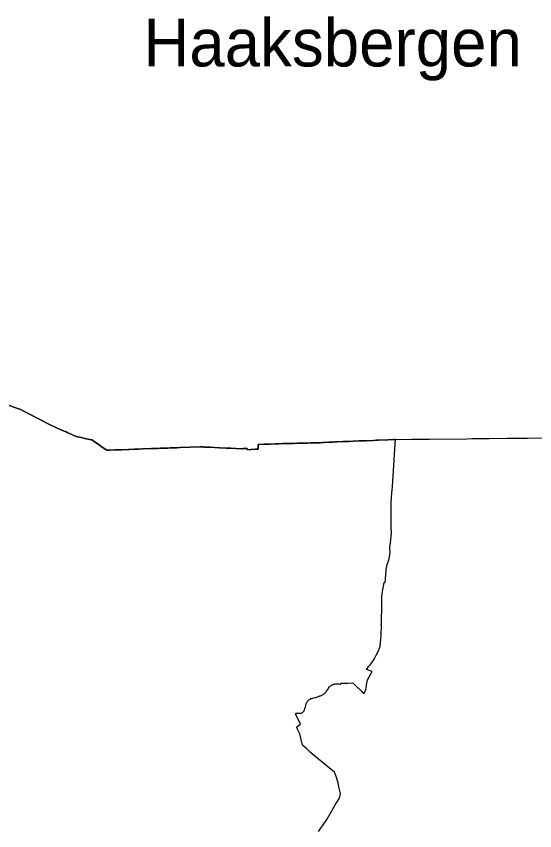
# Model space of a CAD drawing. Extents: x 113371 to 291721, y 393993 to 520143.
# Drawn here: x 245048 to 250494, y 455750 to 464302 of the extents above; entities that cross this region are included whole.
import ezdxf

# ---------------------------------------------------------------- set-up
doc = ezdxf.new("R2010")
doc.units = 0
doc.layers.add('Default', color=7, linetype='Continuous')
doc.layers.add('plaatsnamen', color=7, linetype='Continuous')

msp = doc.modelspace()

# ---------------------------------------------------------------- linework, layer by layer
at = {"layer": 'Default'}
for points in [[(245632.235625, 459909.5825), (245581.605625, 459932.2525), (245581.445625, 459932.3225), (245570.375625, 459937.2225), (245550.985625, 459945.7825), (245478.225625, 459977.9525), (245450.665625, 459990.1325), (245417.505625, 460004.5125), (245395.415625, 460014.0925), (245099.235625, 460169.0625), (245094.315625, 460171.5525), (245083.585625, 460175.5825), (245071.705625, 460180.0525), (244938.645625, 460230.0925)], [(244938.645625, 460230.0925), (245071.705625, 460180.0525), (245083.585625, 460175.5825), (245094.315625, 460171.5525), (245099.235625, 460169.0625), (245395.415625, 460014.0925), (245417.505625, 460004.5125), (245450.665625, 459990.1325), (245478.225625, 459977.9525), (245550.985625, 459945.7825), (245570.375625, 459937.2225), (245581.445625, 459932.3225), (245581.605625, 459932.2525), (245632.235625, 459909.5825), (245651.635625, 459901.3225), (245670.595625, 459892.5425), (245677.315625, 459890.9925), (245677.605625, 459890.9225), (245730.945625, 459878.6125), (245781.805625, 459866.2725), (245839.935625, 459853.1725), (245910.985625, 459805.0225), (245934.645625, 459789.5525), (245939.525625, 459786.2725), (245999.695625, 459745.7925), (246030.245625, 459746.5525), (246085.795625, 459748.4625), (246120.305625, 459750.3025), (246122.365625, 459750.2925), (246125.915625, 459750.2825), (246126.945625, 459750.2825), (246152.785625, 459750.9225), (246225.045625, 459753.6325), (246236.055625, 459753.7425), (246284.385625, 459755.4425), (246332.885625, 459757.3625), (246378.135625, 459759.1425)], [(246726.125625, 459771.2425), (246725.855625, 459771.2325), (246725.795625, 459771.2325), (246720.375625, 459771.0425), (246714.945625, 459770.8625), (246714.035625, 459770.8325), (246669.895625, 459769.3325), (246666.585625, 459769.2125), (246664.055625, 459769.1225), (246638.825625, 459768.2325), (246564.325625, 459765.5825), (246538.825625, 459764.8725), (246534.025625, 459764.7425), (246469.275625, 459762.9425), (246378.135625, 459759.1425), (246332.885625, 459757.3625), (246284.385625, 459755.4425), (246236.055625, 459753.7425), (246225.045625, 459753.6325), (246152.785625, 459750.9225), (246126.945625, 459750.2825), (246125.915625, 459750.2825), (246122.365625, 459750.2925), (246120.305625, 459750.3025), (246085.795625, 459748.4625), (246030.245625, 459746.5525), (245999.695625, 459745.7925), (245939.525625, 459786.2725), (245934.645625, 459789.5525), (245910.985625, 459805.0225), (245839.935625, 459853.1725), (245781.805625, 459866.2725), (245730.945625, 459878.6125), (245677.605625, 459890.9225), (245677.315625, 459890.9925), (245670.595625, 459892.5425), (245651.635625, 459901.3225), (245632.235625, 459909.5825)], [(247849.665625, 459814.9125), (247809.575625, 459813.1025), (247804.315625, 459812.9625), (247769.175625, 459812.0625), (247715.685625, 459810.6925), (247714.085625, 459810.6425), (247651.205625, 459808.8025), (247650.675625, 459808.7825), (247590.185625, 459807.0125), (247590.245625, 459756.7525), (247559.215625, 459755.4525), (247510.195625, 459752.8025), (247477.365625, 459750.7225), (247473.665625, 459764.9525), (247431.995625, 459762.7325), (247412.435625, 459761.3325), (247409.025625, 459761.8325), (247303.035625, 459766.3225), (247265.155625, 459768.2225), (247264.645625, 459768.2425), (247255.265625, 459768.7025), (247253.785625, 459768.7825), (247253.545625, 459768.7925), (247182.185625, 459771.8525), (247080.735625, 459776.4525), (247049.085625, 459777.8225), (247019.375625, 459779.2025), (247009.105625, 459779.6825), (247008.155625, 459779.7325), (247007.555625, 459779.7525), (246998.105625, 459780.1925), (246989.705625, 459780.4025), (246977.915625, 459779.8425), (246874.355625, 459776.3625), (246770.895625, 459772.7625), (246733.865625, 459771.5025), (246726.175625, 459771.2425), (246726.125625, 459771.2425)], [(247431.995625, 459762.7325), (247473.665625, 459764.9525), (247477.365625, 459750.7225), (247510.195625, 459752.8025), (247559.215625, 459755.4525), (247590.245625, 459756.7525), (247590.185625, 459807.0125), (247650.675625, 459808.7825), (247651.205625, 459808.8025), (247714.085625, 459810.6425), (247715.685625, 459810.6925), (247769.175625, 459812.0625), (247804.315625, 459812.9625), (247809.575625, 459813.1025), (247849.665625, 459814.9125), (247886.165625, 459815.5525), (247891.025625, 459815.6325), (247921.135625, 459816.5325), (247930.885625, 459816.8225), (247954.705625, 459817.2125), (247960.845625, 459817.3125), (247997.445625, 459818.2025), (248038.125625, 459819.2025), (248104.805625, 459821.2625), (248140.065625, 459821.8325), (248199.195625, 459823.6225), (248232.185625, 459824.6225), (248238.795625, 459824.8225), (248239.755625, 459824.8525), (248266.185625, 459826.2025)], [(249021.365625, 459699.9125), (249032.395625, 459858.9725), (249009.645625, 459858.2425), (248950.145625, 459855.4625), (248847.875625, 459851.1425), (248835.035625, 459850.5925), (248833.555625, 459850.5425), (248799.065625, 459849.3025), (248721.935625, 459845.7425), (248684.765625, 459843.8625), (248651.285625, 459842.5625), (248587.855625, 459840.1125), (248541.525625, 459838.0125), (248541.325625, 459838.0025), (248478.085625, 459835.4025), (248419.905625, 459832.9725), (248418.725625, 459832.9325), (248398.595625, 459831.9625), (248377.955625, 459830.9625), (248366.255625, 459830.3925), (248332.755625, 459829.0325), (248277.055625, 459826.7625), (248266.185625, 459826.2025), (248239.755625, 459824.8525), (248238.795625, 459824.8225), (248232.185625, 459824.6225), (248199.195625, 459823.6225), (248140.065625, 459821.8325), (248104.805625, 459821.2625), (248038.125625, 459819.2025), (247997.445625, 459818.2025), (247960.845625, 459817.3125), (247954.705625, 459817.2125), (247930.885625, 459816.8225), (247921.135625, 459816.5325), (247891.025625, 459815.6325), (247886.165625, 459815.5525), (247849.665625, 459814.9125)], [(248266.185625, 459826.2025), (248277.055625, 459826.7625), (248332.755625, 459829.0325), (248366.255625, 459830.3925), (248377.955625, 459830.9625), (248398.595625, 459831.9625), (248418.725625, 459832.9325), (248419.905625, 459832.9725), (248478.085625, 459835.4025), (248541.325625, 459838.0025), (248541.525625, 459838.0125), (248587.855625, 459840.1125), (248651.285625, 459842.5625), (248684.765625, 459843.8625), (248721.935625, 459845.7425), (248799.065625, 459849.3025), (248833.555625, 459850.5425), (248835.035625, 459850.5925), (248847.875625, 459851.1425), (248950.145625, 459855.4625), (249009.645625, 459858.2425), (249032.395625, 459858.9725), (249208.575625, 459860.7325), (249213.045625, 459860.7825), (249216.725625, 459860.8125), (249224.285625, 459860.8925), (249389.745625, 459862.5425), (249779.685625, 459866.3925), (249840.825625, 459868.2225), (249864.025625, 459868.9225), (249875.055625, 459868.9125), (249910.755625, 459868.9125), (250017.215625, 459868.9025), (250203.375625, 459870.9425), (250203.535625, 459870.9425), (250227.385625, 459871.1625), (250230.205625, 459871.1925), (250415.405625, 459872.9125)], [(250415.405625, 459872.9125), (250627.735625, 459874.8825)], [(246378.135625, 459759.1425), (246469.275625, 459762.9425), (246534.025625, 459764.7425), (246538.825625, 459764.8725), (246564.325625, 459765.5825), (246638.825625, 459768.2325), (246664.055625, 459769.1225), (246666.585625, 459769.2125), (246669.895625, 459769.3325), (246714.035625, 459770.8325), (246714.945625, 459770.8625), (246720.375625, 459771.0425), (246725.795625, 459771.2325), (246725.855625, 459771.2325), (246726.125625, 459771.2425), (246726.175625, 459771.2425), (246733.865625, 459771.5025), (246770.895625, 459772.7625), (246874.355625, 459776.3625), (246977.915625, 459779.8425), (246989.705625, 459780.4025), (246998.105625, 459780.1925), (247007.555625, 459779.7525), (247008.155625, 459779.7325), (247009.105625, 459779.6825), (247019.375625, 459779.2025), (247049.085625, 459777.8225), (247080.735625, 459776.4525), (247182.185625, 459771.8525), (247253.545625, 459768.7925), (247253.785625, 459768.7825), (247255.265625, 459768.7025), (247264.645625, 459768.2425), (247265.155625, 459768.2225), (247303.035625, 459766.3225), (247409.025625, 459761.8325), (247412.435625, 459761.3325), (247431.995625, 459762.7325)], [(248889.615625, 458128.3825), (248888.105625, 458176.6725), (248889.225625, 458207.4525), (248895.005625, 458260.1525), (248899.305625, 458283.6225), (248906.605625, 458319.1825), (248911.215625, 458358.0025), (248923.275625, 458356.4325), (248933.145625, 458479.8825), (248934.265625, 458498.5825), (248940.665625, 458525.1125), (248945.675625, 458545.8625), (248956.965625, 458583.6225), (248964.395625, 458606.4025), (248974.135625, 458672.1325), (248972.945625, 458709.1925), (248971.945625, 458727.7425), (248979.075625, 458771.4725), (248983.975625, 458803.4025), (248986.385625, 458838.7625), (248988.335625, 458878.7325), (248987.305625, 458937.8125), (248986.015625, 459036.9225), (248984.845625, 459070.7025), (248985.275625, 459100.9425), (248986.165625, 459209.7725), (248988.755625, 459241.3325), (248993.775625, 459301.2225), (248996.205625, 459325.3425), (248999.395625, 459362.8625), (249004.365625, 459427.1325), (249007.085625, 459471.8925), (249007.265625, 459475.0025), (249010.485625, 459527.8125), (249017.885625, 459649.5625), (249017.915625, 459650.0425), (249021.315625, 459699.1925), (249021.365625, 459699.9125)], [(248579.325625, 457302.0625), (248579.905625, 457302.0825), (248582.145625, 457302.1325), (248618.195625, 457268.6025), (248675.555625, 457215.2625), (248701.115625, 457191.0825), (248718.305625, 457233.5425), (248724.245625, 457253.8125), (248727.565625, 457272.0325), (248727.635625, 457272.8425), (248730.285625, 457302.1825), (248733.295625, 457319.8125), (248742.455625, 457342.8325), (248786.005625, 457422.6725), (248728.215625, 457443.6925), (248753.235625, 457476.7125), (248767.335625, 457495.3225), (248770.365625, 457498.1425), (248775.675625, 457503.3625), (248776.805625, 457504.5525), (248800.915625, 457540.5125), (248814.375625, 457564.5325), (248830.005625, 457593.7925), (248852.855625, 457640.4725), (248863.945625, 457667.8825), (248871.615625, 457686.8325), (248870.375625, 457696.7125), (248875.005625, 457720.7425), (248876.205625, 457760.5025), (248881.015625, 457803.0225), (248882.265625, 457829.9325), (248881.325625, 457849.9725), (248883.165625, 457864.9625), (248883.505625, 457871.2725), (248882.945625, 457902.9625), (248882.435625, 457913.6225), (248883.135625, 457921.9725), (248889.615625, 458128.3825)], [(248265.675625, 457177.4725), (248270.785625, 457179.8525), (248274.905625, 457182.7025), (248280.775625, 457186.9825), (248287.075625, 457191.6825), (248289.735625, 457194.2925), (248294.335625, 457199.7425), (248298.875625, 457204.7025), (248302.315625, 457209.3625), (248306.545625, 457216.1825), (248312.715625, 457224.9525), (248319.625625, 457234.4725), (248324.765625, 457242.5125), (248339.995625, 457262.9125), (248343.305625, 457266.7125), (248346.135625, 457269.2725), (248350.715625, 457272.7925), (248355.675625, 457276.4425), (248359.335625, 457278.7925), (248363.955625, 457281.1725), (248368.985625, 457283.4125), (248375.915625, 457286.8325), (248380.005625, 457287.9225), (248385.425625, 457289.4725), (248394.655625, 457290.8425), (248400.745625, 457292.1125), (248406.435625, 457292.8725), (248414.595625, 457293.3825), (248422.845625, 457293.2125), (248429.955625, 457293.2725), (248435.575625, 457293.0725), (248435.825625, 457292.9925), (248447.755625, 457290.3825), (248454.215625, 457289.0825), (248458.625625, 457298.7125), (248525.385625, 457300.7125), (248531.445625, 457300.8925), (248579.325625, 457302.0625)], [(248061.845625, 456998.2325), (248065.725625, 457002.6025), (248068.565625, 457006.1725), (248070.705625, 457009.0625), (248072.545625, 457013.5025), (248074.945625, 457019.2725), (248079.685625, 457035.0125), (248084.855625, 457050.9925), (248089.455625, 457065.9225), (248093.945625, 457081.9925), (248096.705625, 457089.8725), (248099.055625, 457095.1125), (248100.985625, 457099.3025), (248103.865625, 457103.9325), (248106.845625, 457108.3125), (248110.915625, 457113.4225), (248115.185625, 457118.6825), (248118.555625, 457121.8925), (248121.955625, 457125.0225), (248125.105625, 457127.2925), (248128.875625, 457129.9225), (248133.755625, 457132.1825), (248138.695625, 457135.0325), (248143.905625, 457137.0525), (248150.465625, 457139.1325), (248163.825625, 457142.5825), (248171.675625, 457144.9525), (248186.145625, 457148.9125), (248193.965625, 457150.8125), (248201.695625, 457153.3425), (248209.035625, 457155.8525), (248222.825625, 457160.2625), (248229.865625, 457162.5625), (248236.665625, 457164.9625), (248242.615625, 457166.8925), (248249.105625, 457169.8525), (248257.775625, 457173.7525), (248265.675625, 457177.4725)], [(248399.455625, 456020.7825), (248442.165625, 456092.6925), (248452.445625, 456141.8925), (248436.375625, 456212.3925), (248431.325625, 456235.0025), (248427.615625, 456251.5925), (248406.865625, 456319.4925), (248391.865625, 456366.7525), (248301.315625, 456440.0625), (248184.665625, 456534.7425), (248141.265625, 456569.5225), (248095.005625, 456612.4525), (248082.255625, 456624.2525), (248059.735625, 456645.3925), (248056.375625, 456652.8325), (248052.665625, 456662.8125), (248050.675625, 456668.1825), (248048.405625, 456676.5225), (248027.835625, 456767.5525), (247993.165625, 456837.1125), (248034.515625, 456869.2325), (247986.275625, 456970.9825), (247985.005625, 456974.5825), (247985.285625, 456980.4025), (247987.105625, 456983.4525), (247993.285625, 456983.8725), (248004.055625, 456984.4425), (248018.155625, 456984.5625), (248026.995625, 456984.4425), (248031.955625, 456984.5225), (248037.165625, 456984.5325), (248040.405625, 456984.8225), (248042.395625, 456985.3325), (248045.625625, 456986.4925), (248049.025625, 456987.8925), (248053.885625, 456991.2525), (248058.205625, 456994.7925), (248061.845625, 456998.2325)], [(248221.715625, 455742.2925), (248296.085625, 455847.9225), (248303.495625, 455858.4425), (248310.465625, 455869.5525), (248361.925625, 455957.6025), (248399.455625, 456020.7825)]]:
    msp.add_lwpolyline(points, dxfattribs=at)

# ---------------------------------------------------------------- texts
at = {"layer": 'plaatsnamen'}
msp.add_text('Haaksbergen', height=500, dxfattribs=at).set_placement((246382.681779, 463775.189767))

doc.saveas('drawing.dxf')
